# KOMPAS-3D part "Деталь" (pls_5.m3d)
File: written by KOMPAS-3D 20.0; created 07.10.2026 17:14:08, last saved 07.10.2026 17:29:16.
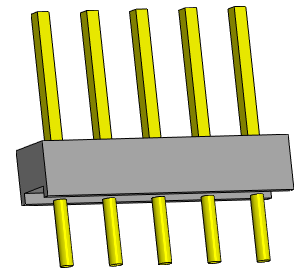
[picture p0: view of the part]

Document properties: Полное имя файла: D:\myProjects\Progect_esp32\box_compas\pls_5.m3d

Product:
- Part/product: Деталь
    Масса: 0.000651758
  - Body: Тело 1
      Масса: 0.000660862

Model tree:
1. Эскиз:1
2. Элемент выдавливания:1
     Расстояние 1 = 2.5
3. Эскиз:2  (with: Элемент выдавливания:1)
4. Элемент выдавливания:2
     Расстояние 1 = 6
5. Массив по сетке:1  (with: Элемент выдавливания:2, Эскиз:2)  (5 pattern instances)
     Шаг 1 = 2.54; Угол раствора = 90
6. Эскиз:3  (with: Элемент выдавливания:1)
7. Элемент выдавливания:3
     Расстояние 1 = 3
8. Массив по сетке:2  (with: Элемент выдавливания:3, Эскиз:3)  (5 pattern instances)
     Шаг 1 = 2.54; Угол раствора = 90; Геометрический массив = 128
9. Эскиз:4  (with: Элемент выдавливания:1)
10. Элемент выдавливания:4
     Расстояние 2 = 12.7
11. Элемент выдавливания:5
     Расстояние 1 = 3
